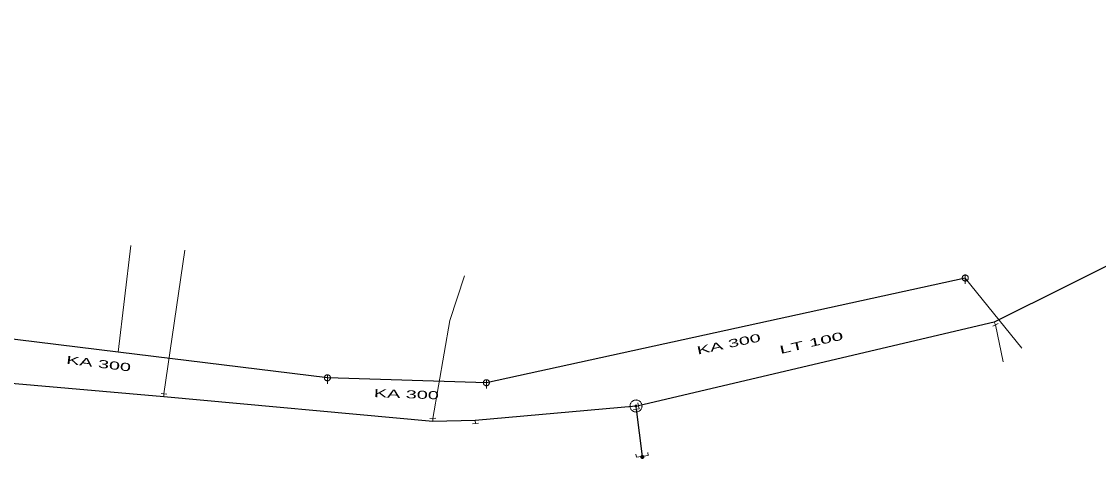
# Model space of a CAD drawing. Extents: x -687468 to -685917, y -974192 to -973456.
# Drawn here: x -686341.5 to -686251.8, y -973626.2 to -973589.8 of the extents above; entities that cross this region are included whole.
import ezdxf
from ezdxf.enums import TextEntityAlignment as Align

# ---------------------------------------------------------------- set-up
doc = ezdxf.new("R2010")
doc.units = 0
doc.header["$LTSCALE"] = 0.27
for name, color, linetype, lineweight in [('1', 7, 'Continuous', 13), ('11', 7, 'Continuous', 13), ('13', 7, 'Continuous', 13), ('14', 7, 'Continuous', 25), ('17', 7, 'Continuous', 25), ('22', 7, 'Continuous', 13), ('34', 7, 'Continuous', 13), ('47', 7, 'Continuous', 13), ('9', 7, 'Continuous', 13)]:
    doc.layers.add(name, color=color, linetype=linetype, lineweight=lineweight)

msp = doc.modelspace()

# ---------------------------------------------------------------- linework, layer by layer
at = {"layer": '11'}
for p, q in [((-686332.44, -973608.46), (-686333.511, -973617.333)), ((-686258.239, -973616.989), (-686262.94, -973611.16))]:
    msp.add_line(p, q, dxfattribs=at)
at = {"layer": '13'}
for p, q in [((-686329.686, -973620.81), (-686327.96, -973608.829)), ((-686260.418, -973615.073), (-686259.78, -973618.129))]:
    msp.add_line(p, q, dxfattribs=at)
msp.add_lwpolyline([(-686307.295, -973622.849), (-686305.87, -973614.71), (-686304.649, -973610.969)], dxfattribs=at)
at = {"layer": '14'}
for p, q in [((-686262.94, -973611.16), (-686302.829, -973619.879)), ((-686302.829, -973619.879), (-686316.07, -973619.469))]:
    msp.add_line(p, q, dxfattribs=at)
at = {"layer": '14', "lineweight": 13}
for p, q in [((-686260.418, -973615.073), (-686260.53, -973614.85)), ((-686329.686, -973620.81), (-686329.71, -973621.059)), ((-686290.159, -973621.799), (-686290.363, -973621.818)), ((-686290.363, -973621.818), (-686290.34, -973622.079)), ((-686307.295, -973622.849), (-686307.289, -973623.1)), ((-686303.727, -973623.268), (-686303.75, -973623.02)), ((-686289.845, -973626.011), (-686289.839, -973626.059))]:
    msp.add_line(p, q, dxfattribs=at)
at = {"layer": '14'}
msp.add_lwpolyline([(-686316.07, -973619.469), (-686333.511, -973617.333), (-686353.859, -973614.84)], dxfattribs=at)
at = {"layer": '17'}
msp.add_line((-686290.34, -973622.079), (-686289.845, -973626.011), dxfattribs=at)
for points in [[(-686215.348, -973589.807), (-686215.489, -973589.889), (-686241.84, -973605.539), (-686260.53, -973614.85), (-686290.159, -973621.799)], [(-686290.363, -973621.818), (-686303.75, -973623.02), (-686307.289, -973623.1), (-686329.71, -973621.059), (-686345.609, -973619.67), (-686377.789, -973616.6), (-686380.539, -973616.899), (-686396.199, -973617.51)]]:
    msp.add_lwpolyline(points, dxfattribs=at)
at = {"layer": '22'}
for p, q in [((-686262.939, -973610.908), (-686262.94, -973611.652)), ((-686316.069, -973619.217), (-686316.07, -973619.961)), ((-686302.828, -973619.627), (-686302.829, -973620.37))]:
    msp.add_line(p, q, dxfattribs=at)
for points in [[(-686262.688, -973611.16), (-686262.689, -973611.134), (-686262.693, -973611.108), (-686262.699, -973611.082), (-686262.709, -973611.058), (-686262.721, -973611.034), (-686262.735, -973611.012), (-686262.752, -973610.991), (-686262.77, -973610.973), (-686262.791, -973610.956), (-686262.813, -973610.942), (-686262.837, -973610.93), (-686262.861, -973610.92), (-686262.887, -973610.914), (-686262.913, -973610.91), (-686262.939, -973610.908), (-686262.965, -973610.909), (-686262.991, -973610.913), (-686263.017, -973610.919), (-686263.042, -973610.929), (-686263.065, -973610.941), (-686263.087, -973610.955), (-686263.108, -973610.972), (-686263.126, -973610.99), (-686263.143, -973611.011), (-686263.157, -973611.033), (-686263.169, -973611.057), (-686263.179, -973611.081), (-686263.186, -973611.107), (-686263.19, -973611.133), (-686263.191, -973611.159), (-686263.191, -973611.185), (-686263.187, -973611.211), (-686263.18, -973611.237), (-686263.17, -973611.262), (-686263.158, -973611.285), (-686263.144, -973611.307), (-686263.127, -973611.328), (-686263.109, -973611.346), (-686263.088, -973611.363), (-686263.066, -973611.377), (-686263.043, -973611.389), (-686263.018, -973611.399), (-686262.992, -973611.406), (-686262.966, -973611.41), (-686262.94, -973611.412), (-686262.914, -973611.411), (-686262.888, -973611.407), (-686262.862, -973611.4), (-686262.838, -973611.39), (-686262.814, -973611.378), (-686262.792, -973611.364), (-686262.771, -973611.347), (-686262.753, -973611.329), (-686262.736, -973611.308), (-686262.722, -973611.286), (-686262.71, -973611.263), (-686262.7, -973611.238), (-686262.694, -973611.212), (-686262.69, -973611.186)], [(-686315.818, -973619.469), (-686315.819, -973619.443), (-686315.823, -973619.417), (-686315.829, -973619.391), (-686315.839, -973619.367), (-686315.851, -973619.343), (-686315.865, -973619.321), (-686315.882, -973619.3), (-686315.9, -973619.282), (-686315.921, -973619.265), (-686315.943, -973619.251), (-686315.967, -973619.239), (-686315.991, -973619.229), (-686316.017, -973619.223), (-686316.043, -973619.219), (-686316.069, -973619.217), (-686316.095, -973619.218), (-686316.121, -973619.222), (-686316.147, -973619.228), (-686316.172, -973619.238), (-686316.195, -973619.25), (-686316.217, -973619.264), (-686316.238, -973619.281), (-686316.256, -973619.299), (-686316.273, -973619.32), (-686316.287, -973619.342), (-686316.299, -973619.366), (-686316.309, -973619.39), (-686316.316, -973619.416), (-686316.32, -973619.442), (-686316.321, -973619.468), (-686316.321, -973619.494), (-686316.317, -973619.52), (-686316.31, -973619.546), (-686316.3, -973619.571), (-686316.288, -973619.594), (-686316.274, -973619.616), (-686316.257, -973619.637), (-686316.239, -973619.655), (-686316.218, -973619.672), (-686316.196, -973619.686), (-686316.173, -973619.698), (-686316.148, -973619.708), (-686316.122, -973619.715), (-686316.096, -973619.719), (-686316.07, -973619.721), (-686316.044, -973619.72), (-686316.018, -973619.716), (-686315.992, -973619.709), (-686315.968, -973619.699), (-686315.944, -973619.687), (-686315.922, -973619.673), (-686315.901, -973619.656), (-686315.883, -973619.638), (-686315.866, -973619.617), (-686315.852, -973619.595), (-686315.84, -973619.572), (-686315.83, -973619.547), (-686315.824, -973619.521), (-686315.82, -973619.495)], [(-686302.577, -973619.879), (-686302.578, -973619.853), (-686302.582, -973619.827), (-686302.588, -973619.801), (-686302.598, -973619.777), (-686302.61, -973619.753), (-686302.624, -973619.731), (-686302.641, -973619.71), (-686302.659, -973619.692), (-686302.68, -973619.675), (-686302.702, -973619.661), (-686302.726, -973619.649), (-686302.75, -973619.639), (-686302.776, -973619.633), (-686302.802, -973619.629), (-686302.828, -973619.627), (-686302.854, -973619.628), (-686302.88, -973619.632), (-686302.906, -973619.638), (-686302.931, -973619.648), (-686302.954, -973619.66), (-686302.976, -973619.674), (-686302.997, -973619.691), (-686303.015, -973619.709), (-686303.032, -973619.73), (-686303.046, -973619.752), (-686303.058, -973619.776), (-686303.068, -973619.8), (-686303.075, -973619.826), (-686303.079, -973619.852), (-686303.081, -973619.878), (-686303.08, -973619.904), (-686303.076, -973619.93), (-686303.069, -973619.956), (-686303.059, -973619.981), (-686303.047, -973620.004), (-686303.033, -973620.026), (-686303.016, -973620.047), (-686302.998, -973620.065), (-686302.977, -973620.082), (-686302.955, -973620.096), (-686302.932, -973620.108), (-686302.907, -973620.118), (-686302.881, -973620.125), (-686302.855, -973620.129), (-686302.829, -973620.13), (-686302.803, -973620.13), (-686302.777, -973620.126), (-686302.751, -973620.119), (-686302.727, -973620.109), (-686302.703, -973620.097), (-686302.681, -973620.083), (-686302.66, -973620.066), (-686302.642, -973620.048), (-686302.625, -973620.027), (-686302.611, -973620.005), (-686302.599, -973619.982), (-686302.589, -973619.957), (-686302.583, -973619.931), (-686302.579, -973619.905)]]:
    msp.add_lwpolyline(points, close=True, dxfattribs=at)
at = {"layer": '34'}
for p, q in [((-686260.64, -973615.183), (-686260.195, -973614.962)), ((-686329.439, -973620.832), (-686329.932, -973620.787)), ((-686290.587, -973622.1), (-686290.092, -973622.057)), ((-686290.102, -973622.04), (-686290.215, -973621.557)), ((-686307.542, -973622.854), (-686307.047, -973622.843)), ((-686303.974, -973623.289), (-686303.479, -973623.246))]:
    msp.add_line(p, q, dxfattribs=at)
at = {"layer": '47'}
for points in [[(-686289.863, -973621.818), (-686289.866, -973621.766), (-686289.874, -973621.713), (-686289.888, -973621.664), (-686289.906, -973621.615), (-686289.93, -973621.568), (-686289.959, -973621.524), (-686289.992, -973621.483), (-686290.029, -973621.446), (-686290.069, -973621.414), (-686290.113, -973621.385), (-686290.16, -973621.36), (-686290.209, -973621.343), (-686290.259, -973621.329), (-686290.311, -973621.321), (-686290.363, -973621.318), (-686290.415, -973621.321), (-686290.467, -973621.329), (-686290.518, -973621.343), (-686290.566, -973621.36), (-686290.613, -973621.385), (-686290.657, -973621.414), (-686290.698, -973621.446), (-686290.735, -973621.483), (-686290.768, -973621.524), (-686290.796, -973621.568), (-686290.82, -973621.615), (-686290.839, -973621.664), (-686290.852, -973621.713), (-686290.86, -973621.766), (-686290.863, -973621.818), (-686290.86, -973621.87), (-686290.852, -973621.922), (-686290.839, -973621.973), (-686290.82, -973622.021), (-686290.796, -973622.068), (-686290.768, -973622.112), (-686290.735, -973622.152), (-686290.698, -973622.19), (-686290.657, -973622.223), (-686290.613, -973622.25), (-686290.566, -973622.275), (-686290.518, -973622.294), (-686290.467, -973622.306), (-686290.415, -973622.315), (-686290.363, -973622.318), (-686290.311, -973622.315), (-686290.259, -973622.306), (-686290.209, -973622.294), (-686290.16, -973622.275), (-686290.113, -973622.25), (-686290.069, -973622.223), (-686290.029, -973622.19), (-686289.992, -973622.152), (-686289.959, -973622.112), (-686289.93, -973622.068), (-686289.906, -973622.021), (-686289.888, -973621.973), (-686289.874, -973621.922), (-686289.866, -973621.87)], [(-686290.281, -973621.818), (-686290.281, -973621.809), (-686290.283, -973621.801), (-686290.285, -973621.793), (-686290.288, -973621.784), (-686290.292, -973621.777), (-686290.297, -973621.77), (-686290.302, -973621.762), (-686290.308, -973621.757), (-686290.315, -973621.752), (-686290.322, -973621.747), (-686290.33, -973621.743), (-686290.338, -973621.74), (-686290.346, -973621.738), (-686290.354, -973621.735), (-686290.363, -973621.735), (-686290.372, -973621.735), (-686290.38, -973621.738), (-686290.388, -973621.74), (-686290.396, -973621.743), (-686290.404, -973621.747), (-686290.411, -973621.752), (-686290.418, -973621.757), (-686290.424, -973621.762), (-686290.43, -973621.77), (-686290.434, -973621.777), (-686290.438, -973621.784), (-686290.441, -973621.793), (-686290.443, -973621.801), (-686290.445, -973621.809), (-686290.445, -973621.818), (-686290.445, -973621.826), (-686290.443, -973621.835), (-686290.441, -973621.843), (-686290.438, -973621.851), (-686290.434, -973621.858), (-686290.43, -973621.865), (-686290.424, -973621.873), (-686290.418, -973621.879), (-686290.411, -973621.885), (-686290.404, -973621.889), (-686290.396, -973621.892), (-686290.388, -973621.896), (-686290.38, -973621.897), (-686290.372, -973621.9), (-686290.363, -973621.9), (-686290.354, -973621.9), (-686290.346, -973621.897), (-686290.338, -973621.896), (-686290.33, -973621.892), (-686290.322, -973621.889), (-686290.315, -973621.885), (-686290.308, -973621.879), (-686290.302, -973621.873), (-686290.297, -973621.865), (-686290.292, -973621.858), (-686290.288, -973621.851), (-686290.285, -973621.843), (-686290.283, -973621.835), (-686290.281, -973621.826)]]:
    msp.add_lwpolyline(points, close=True, dxfattribs=at)
msp.add_lwpolyline([(-686289.384, -973625.699), (-686289.352, -973625.949), (-686290.337, -973626.072), (-686290.368, -973625.822)], dxfattribs=at)
at = {"layer": '9'}
for points in [[(-686289.713, -973626.059), (-686289.714, -973626.046), (-686289.716, -973626.033), (-686289.719, -973626.02), (-686289.724, -973626.008), (-686289.73, -973625.996), (-686289.737, -973625.985), (-686289.745, -973625.975), (-686289.755, -973625.965), (-686289.765, -973625.957), (-686289.776, -973625.95), (-686289.788, -973625.944), (-686289.8, -973625.939), (-686289.813, -973625.936), (-686289.826, -973625.934), (-686289.839, -973625.933), (-686289.852, -973625.934), (-686289.865, -973625.936), (-686289.878, -973625.939), (-686289.89, -973625.944), (-686289.902, -973625.95), (-686289.913, -973625.957), (-686289.923, -973625.965), (-686289.933, -973625.975), (-686289.941, -973625.985), (-686289.948, -973625.996), (-686289.954, -973626.008), (-686289.959, -973626.02), (-686289.962, -973626.033), (-686289.964, -973626.046), (-686289.965, -973626.059), (-686289.964, -973626.072), (-686289.962, -973626.085), (-686289.959, -973626.098), (-686289.954, -973626.11), (-686289.948, -973626.122), (-686289.941, -973626.133), (-686289.933, -973626.143), (-686289.923, -973626.153), (-686289.913, -973626.161), (-686289.902, -973626.168), (-686289.89, -973626.174), (-686289.878, -973626.179), (-686289.865, -973626.182), (-686289.852, -973626.184), (-686289.839, -973626.185), (-686289.826, -973626.184), (-686289.813, -973626.182), (-686289.8, -973626.179), (-686289.788, -973626.174), (-686289.776, -973626.168), (-686289.765, -973626.161), (-686289.755, -973626.153), (-686289.745, -973626.143), (-686289.737, -973626.133), (-686289.73, -973626.122), (-686289.724, -973626.11), (-686289.719, -973626.098), (-686289.716, -973626.085), (-686289.714, -973626.072)], [(-686289.733, -973626.059), (-686289.733, -973626.048), (-686289.735, -973626.037), (-686289.738, -973626.026), (-686289.742, -973626.016), (-686289.747, -973626.006), (-686289.753, -973625.997), (-686289.76, -973625.988), (-686289.768, -973625.98), (-686289.777, -973625.973), (-686289.786, -973625.967), (-686289.796, -973625.962), (-686289.806, -973625.958), (-686289.817, -973625.955), (-686289.828, -973625.953), (-686289.839, -973625.953), (-686289.85, -973625.953), (-686289.861, -973625.955), (-686289.872, -973625.958), (-686289.882, -973625.962), (-686289.892, -973625.967), (-686289.901, -973625.973), (-686289.91, -973625.98), (-686289.918, -973625.988), (-686289.925, -973625.997), (-686289.931, -973626.006), (-686289.936, -973626.016), (-686289.94, -973626.026), (-686289.943, -973626.037), (-686289.945, -973626.048), (-686289.945, -973626.059), (-686289.945, -973626.07), (-686289.943, -973626.081), (-686289.94, -973626.092), (-686289.936, -973626.102), (-686289.931, -973626.112), (-686289.925, -973626.121), (-686289.918, -973626.13), (-686289.91, -973626.138), (-686289.901, -973626.145), (-686289.892, -973626.151), (-686289.882, -973626.156), (-686289.872, -973626.16), (-686289.861, -973626.163), (-686289.85, -973626.165), (-686289.839, -973626.165), (-686289.828, -973626.165), (-686289.817, -973626.163), (-686289.806, -973626.16), (-686289.796, -973626.156), (-686289.786, -973626.151), (-686289.777, -973626.145), (-686289.768, -973626.138), (-686289.76, -973626.13), (-686289.753, -973626.121), (-686289.747, -973626.112), (-686289.742, -973626.102), (-686289.738, -973626.092), (-686289.735, -973626.081), (-686289.733, -973626.07)], [(-686289.752, -973626.059), (-686289.753, -973626.05), (-686289.754, -973626.041), (-686289.757, -973626.032), (-686289.76, -973626.024), (-686289.764, -973626.016), (-686289.769, -973626.008), (-686289.775, -973626.001), (-686289.781, -973625.995), (-686289.788, -973625.989), (-686289.796, -973625.984), (-686289.804, -973625.98), (-686289.812, -973625.977), (-686289.821, -973625.974), (-686289.83, -973625.973), (-686289.839, -973625.972), (-686289.848, -973625.973), (-686289.857, -973625.974), (-686289.866, -973625.977), (-686289.874, -973625.98), (-686289.882, -973625.984), (-686289.89, -973625.989), (-686289.897, -973625.995), (-686289.903, -973626.001), (-686289.909, -973626.008), (-686289.914, -973626.016), (-686289.918, -973626.024), (-686289.921, -973626.032), (-686289.924, -973626.041), (-686289.925, -973626.05), (-686289.926, -973626.059), (-686289.925, -973626.068), (-686289.924, -973626.077), (-686289.921, -973626.086), (-686289.918, -973626.094), (-686289.914, -973626.102), (-686289.909, -973626.11), (-686289.903, -973626.117), (-686289.897, -973626.123), (-686289.89, -973626.129), (-686289.882, -973626.134), (-686289.874, -973626.138), (-686289.866, -973626.141), (-686289.857, -973626.144), (-686289.848, -973626.145), (-686289.839, -973626.146), (-686289.83, -973626.145), (-686289.821, -973626.144), (-686289.812, -973626.141), (-686289.804, -973626.138), (-686289.796, -973626.134), (-686289.788, -973626.129), (-686289.781, -973626.123), (-686289.775, -973626.117), (-686289.769, -973626.11), (-686289.764, -973626.102), (-686289.76, -973626.094), (-686289.757, -973626.086), (-686289.754, -973626.077), (-686289.753, -973626.068)], [(-686289.772, -973626.059), (-686289.772, -973626.052), (-686289.774, -973626.045), (-686289.775, -973626.038), (-686289.778, -973626.032), (-686289.781, -973626.026), (-686289.785, -973626.02), (-686289.789, -973626.014), (-686289.794, -973626.009), (-686289.8, -973626.005), (-686289.806, -973626.001), (-686289.812, -973625.998), (-686289.818, -973625.995), (-686289.825, -973625.994), (-686289.832, -973625.992), (-686289.839, -973625.992), (-686289.846, -973625.992), (-686289.853, -973625.994), (-686289.86, -973625.995), (-686289.866, -973625.998), (-686289.873, -973626.001), (-686289.878, -973626.005), (-686289.884, -973626.009), (-686289.889, -973626.014), (-686289.893, -973626.02), (-686289.897, -973626.026), (-686289.9, -973626.032), (-686289.903, -973626.038), (-686289.905, -973626.045), (-686289.906, -973626.052), (-686289.906, -973626.059), (-686289.906, -973626.066), (-686289.905, -973626.073), (-686289.903, -973626.08), (-686289.9, -973626.086), (-686289.897, -973626.093), (-686289.893, -973626.098), (-686289.889, -973626.104), (-686289.884, -973626.109), (-686289.878, -973626.113), (-686289.873, -973626.117), (-686289.866, -973626.12), (-686289.86, -973626.123), (-686289.853, -973626.125), (-686289.846, -973626.126), (-686289.839, -973626.126), (-686289.832, -973626.126), (-686289.825, -973626.125), (-686289.818, -973626.123), (-686289.812, -973626.12), (-686289.806, -973626.117), (-686289.8, -973626.113), (-686289.794, -973626.109), (-686289.789, -973626.104), (-686289.785, -973626.098), (-686289.781, -973626.093), (-686289.778, -973626.086), (-686289.775, -973626.08), (-686289.774, -973626.073), (-686289.772, -973626.066)], [(-686289.792, -973626.059), (-686289.792, -973626.054), (-686289.793, -973626.049), (-686289.794, -973626.044), (-686289.796, -973626.04), (-686289.798, -973626.035), (-686289.801, -973626.031), (-686289.804, -973626.028), (-686289.808, -973626.024), (-686289.811, -973626.021), (-686289.815, -973626.018), (-686289.82, -973626.016), (-686289.824, -973626.014), (-686289.829, -973626.013), (-686289.834, -973626.012), (-686289.839, -973626.012), (-686289.844, -973626.012), (-686289.849, -973626.013), (-686289.854, -973626.014), (-686289.858, -973626.016), (-686289.863, -973626.018), (-686289.867, -973626.021), (-686289.871, -973626.024), (-686289.874, -973626.028), (-686289.877, -973626.031), (-686289.88, -973626.035), (-686289.882, -973626.04), (-686289.884, -973626.044), (-686289.885, -973626.049), (-686289.886, -973626.054), (-686289.886, -973626.059), (-686289.886, -973626.064), (-686289.885, -973626.069), (-686289.884, -973626.074), (-686289.882, -973626.078), (-686289.88, -973626.083), (-686289.877, -973626.087), (-686289.874, -973626.091), (-686289.871, -973626.094), (-686289.867, -973626.097), (-686289.863, -973626.1), (-686289.858, -973626.102), (-686289.854, -973626.104), (-686289.849, -973626.105), (-686289.844, -973626.106), (-686289.839, -973626.106), (-686289.834, -973626.106), (-686289.829, -973626.105), (-686289.824, -973626.104), (-686289.82, -973626.102), (-686289.815, -973626.1), (-686289.811, -973626.097), (-686289.808, -973626.094), (-686289.804, -973626.091), (-686289.801, -973626.087), (-686289.798, -973626.083), (-686289.796, -973626.078), (-686289.794, -973626.074), (-686289.793, -973626.069), (-686289.792, -973626.064)], [(-686289.812, -973626.059), (-686289.812, -973626.056), (-686289.812, -973626.053), (-686289.813, -973626.051), (-686289.814, -973626.048), (-686289.815, -973626.045), (-686289.817, -973626.043), (-686289.819, -973626.041), (-686289.821, -973626.039), (-686289.823, -973626.037), (-686289.825, -973626.035), (-686289.828, -973626.034), (-686289.831, -973626.033), (-686289.833, -973626.032), (-686289.836, -973626.032), (-686289.839, -973626.032), (-686289.842, -973626.032), (-686289.845, -973626.032), (-686289.848, -973626.033), (-686289.85, -973626.034), (-686289.853, -973626.035), (-686289.855, -973626.037), (-686289.858, -973626.039), (-686289.86, -973626.041), (-686289.861, -973626.043), (-686289.863, -973626.045), (-686289.864, -973626.048), (-686289.865, -973626.051), (-686289.866, -973626.053), (-686289.866, -973626.056), (-686289.867, -973626.059), (-686289.866, -973626.062), (-686289.866, -973626.065), (-686289.865, -973626.068), (-686289.864, -973626.07), (-686289.863, -973626.073), (-686289.861, -973626.075), (-686289.86, -973626.078), (-686289.858, -973626.08), (-686289.855, -973626.081), (-686289.853, -973626.083), (-686289.85, -973626.084), (-686289.848, -973626.085), (-686289.845, -973626.086), (-686289.842, -973626.086), (-686289.839, -973626.087), (-686289.836, -973626.086), (-686289.833, -973626.086), (-686289.831, -973626.085), (-686289.828, -973626.084), (-686289.825, -973626.083), (-686289.823, -973626.081), (-686289.821, -973626.08), (-686289.819, -973626.078), (-686289.817, -973626.075), (-686289.815, -973626.073), (-686289.814, -973626.07), (-686289.813, -973626.068), (-686289.812, -973626.065), (-686289.812, -973626.062)], [(-686289.831, -973626.059), (-686289.831, -973626.058), (-686289.831, -973626.057), (-686289.832, -973626.057), (-686289.832, -973626.056), (-686289.832, -973626.055), (-686289.833, -973626.054), (-686289.833, -973626.054), (-686289.834, -973626.053), (-686289.834, -973626.053), (-686289.835, -973626.052), (-686289.836, -973626.052), (-686289.837, -973626.052), (-686289.837, -973626.051), (-686289.838, -973626.051), (-686289.839, -973626.051), (-686289.84, -973626.051), (-686289.841, -973626.051), (-686289.841, -973626.052), (-686289.842, -973626.052), (-686289.843, -973626.052), (-686289.844, -973626.053), (-686289.844, -973626.053), (-686289.845, -973626.054), (-686289.845, -973626.054), (-686289.846, -973626.055), (-686289.846, -973626.056), (-686289.847, -973626.057), (-686289.847, -973626.057), (-686289.847, -973626.058), (-686289.847, -973626.059), (-686289.847, -973626.06), (-686289.847, -973626.061), (-686289.847, -973626.061), (-686289.846, -973626.062), (-686289.846, -973626.063), (-686289.845, -973626.064), (-686289.845, -973626.064), (-686289.844, -973626.065), (-686289.844, -973626.065), (-686289.843, -973626.066), (-686289.842, -973626.066), (-686289.841, -973626.067), (-686289.841, -973626.067), (-686289.84, -973626.067), (-686289.839, -973626.067), (-686289.838, -973626.067), (-686289.837, -973626.067), (-686289.837, -973626.067), (-686289.836, -973626.066), (-686289.835, -973626.066), (-686289.834, -973626.065), (-686289.834, -973626.065), (-686289.833, -973626.064), (-686289.833, -973626.064), (-686289.832, -973626.063), (-686289.832, -973626.062), (-686289.832, -973626.061), (-686289.831, -973626.061), (-686289.831, -973626.06)]]:
    msp.add_lwpolyline(points, close=True, dxfattribs=at)

# ---------------------------------------------------------------- texts
at = {"layer": '1'}
for s, rotation, width, p in [('KA 300', 12, 1.85, (-686282.572, -973616.981)), ('LT 100', 13, 1.95, (-686275.686, -973616.88)), ('KA 300', 353, 1.85, (-686335.165, -973618.619)), ('KA 300', 358, 1.85, (-686309.505, -973621.169))]:
    msp.add_text(s, height=0.6667, rotation=rotation, dxfattribs=dict(at, width=width)).set_placement(p, align=Align.CENTER)

doc.saveas('drawing.dxf')
